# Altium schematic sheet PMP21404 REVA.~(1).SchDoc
size 431 x 279 mm; Date: Not shown in title block; ApprovedBy: Not shown in title block; CheckedBy: Not shown in title block; Author: Not shown in title block; CompanyName: Not shown in title block; Engineer: Not shown in title block; Organization: Not shown in title block; Address1: Not shown in title block; Address2: Not shown in title block; Address3: Not shown in title block; Address4: Not shown in title block; DocumentNumber: 1; Revision: Use project parameter SCH_Rev; SheetNumber: 1; SheetTotal: 1; PageSetup: Record=PageOptions¦CenterHorizontal=True¦CenterVertical=True¦PrintScale=1.00¦XCorrection=1.00¦YCorrection=1.00¦PrintKind=0¦BorderSize=5000000¦LeftOffset=0¦BottomOffset=0¦Orientation=2¦PaperLength=1000¦PaperWidth=1000¦Scale=100¦PaperSource=15¦PrintQuality=600¦MediaType=1¦DitherType=10¦PaperKind=Letter¦PrintScaleMode=1
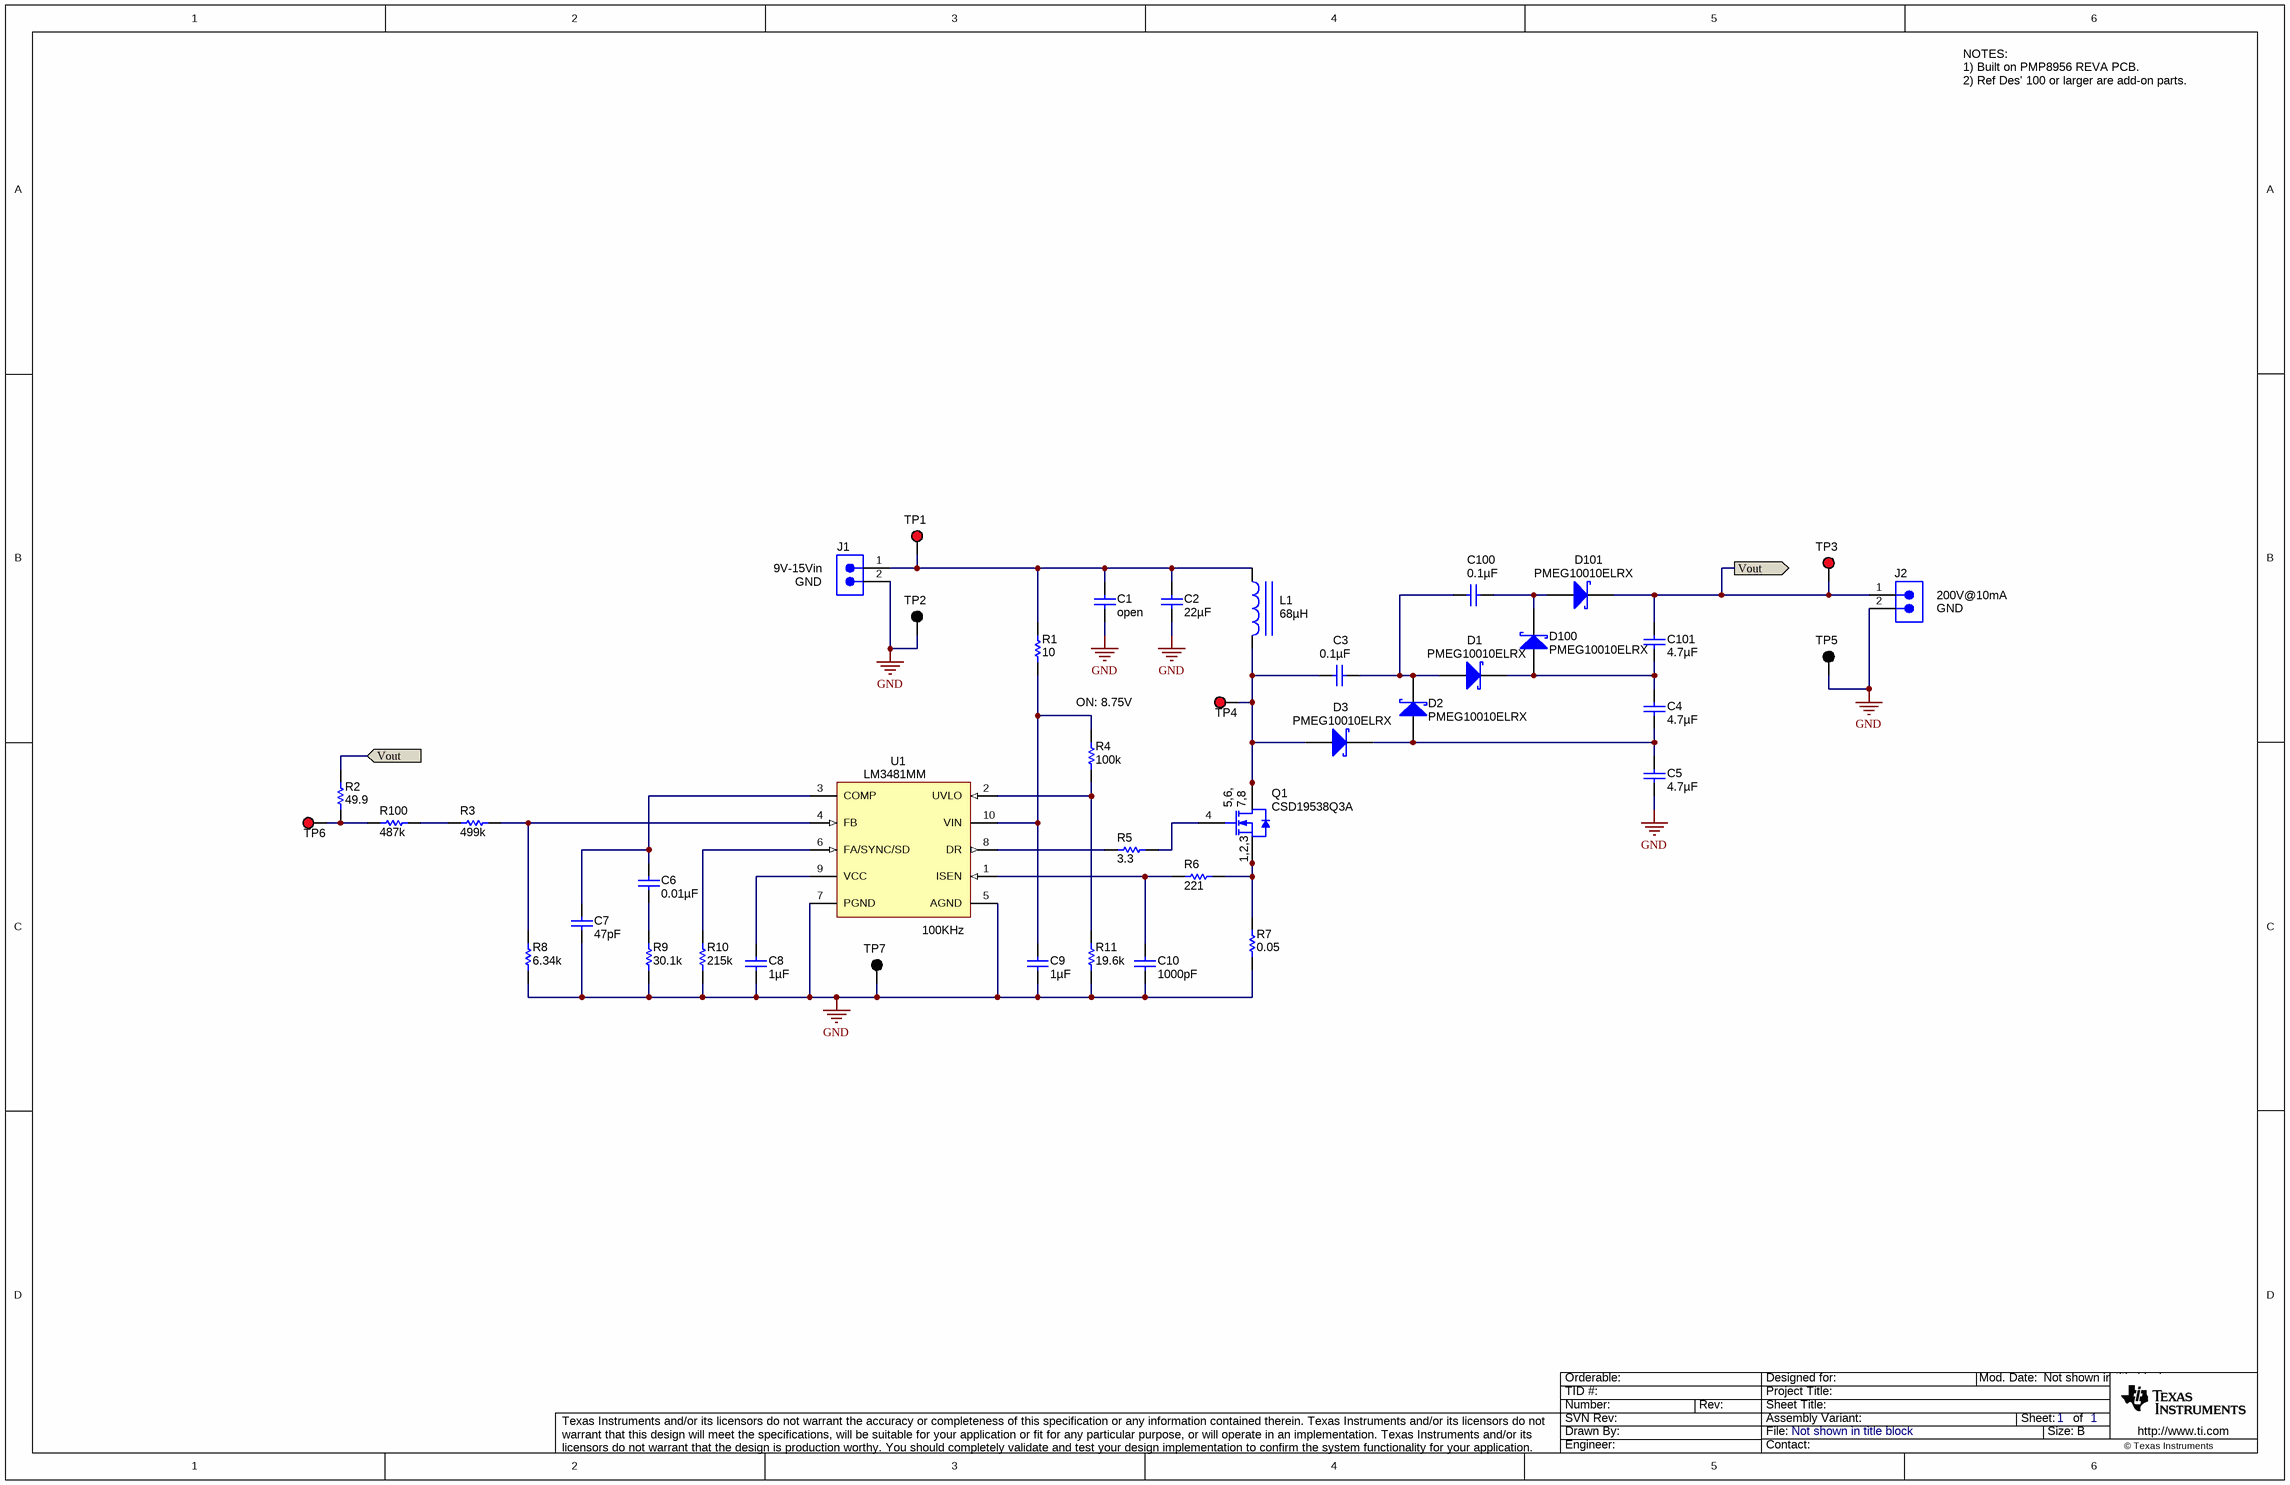
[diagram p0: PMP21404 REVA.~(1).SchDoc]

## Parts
C1  ValueDisplayed: open  [1206L]
C2  ValueDisplayed: 22µF  [1210]  (hidden comment: GRM32ER71E226ME15)
C3  ValueDisplayed: 0.1µF  [0805_HV]  (hidden comment: C2012X7R2A104K)
C4  ValueDisplayed: 4.7µF  [1210]  (hidden comment: C3225X7S2A475M)
C5  ValueDisplayed: 4.7µF  [1210]  (hidden comment: C3225X7S2A475M)
C6  ValueDisplayed: 0.01µF  [0603]  (hidden comment: C1608X7R1H103K)
C7  ValueDisplayed: 47pF  [0603]  (hidden comment: C1608C0G1H470J)
C8  ValueDisplayed: 1µF  [0603L]  (hidden comment: C1608X7R1C105K)
C9  ValueDisplayed: 1µF  [0805L]  (hidden comment: GRM21BR71H105KA12L)
C10  ValueDisplayed: 1000pF  [0603L]  (hidden comment: C1608X7R1H102K)
C100  ValueDisplayed: 0.1µF  [0805_HV]  (hidden comment: C2012X7R2A104K)
C101  ValueDisplayed: 4.7µF  [1210]  (hidden comment: C3225X7S2A475M)
D1  PMEG10010ELRX  [SOD-123W]
D2  PMEG10010ELRX  [SOD-123W]
D3  PMEG10010ELRX  [SOD-123W]
D100  PMEG10010ELRX  [SOD-123W]
D101  PMEG10010ELRX  [SOD-123W]
J1  ED555/2DS  [TERM_BLK_ED555-2DS]  (value not drawn)
J2  ED555/2DS  [TERM_BLK_ED555-2DS]  (value not drawn)
L1  ValueDisplayed: 68µH  [CLF7045]  (hidden comment: CLF7045NIT-680M-D)
Q1  CSD19538Q3A  [DNH0008A]
R1  value 10  [0603L]  (hidden comment: CRCW060310R0JNEA)
R2  value 49.9  [0603L]  (hidden comment: CRCW060349R9FKEA)
R3  ValueDisplayed: 499k  [0805_HV]  (hidden comment: CRCW0805499KFKEA)
R4  value 100k  [0603L]  (hidden comment: CRCW0603100KFKEA)
R5  ValueDisplayed: 3.3  [0603]  (hidden comment: CRCW06033R30JNEA)
R6  value 221  [0603L]  (hidden comment: CRCW0603221RFKEA)
R7  value 0.05  [0805L]  (hidden comment: CRM0805-FW-R050ELF)
R8  ValueDisplayed: 6.34k  [0603L]  (hidden comment: CRCW06036K34FKEA)
R9  ValueDisplayed: 30.1k  [0603]  (hidden comment: CRCW060330K1FKEA)
R10  value 215k  [0603]  (hidden comment: CRCW0603215KFKEA)
R11  value 19.6k  [0603L]  (hidden comment: CRCW060319K6FKEA)
R100  ValueDisplayed: 487k  [0805_HV]  (hidden comment: CRCW0805487KFKEA)
TP1  5000  [Keystone5000]  (value not drawn)
TP2  5001  [Keystone5001]  (value not drawn)
TP3  5000  [Keystone5000]  (value not drawn)
TP4  5000  [Keystone5000]  (value not drawn)
TP5  5001  [Keystone5001]  (value not drawn)
TP6  5000  [Keystone5000]  (value not drawn)
TP7  5001  [Keystone5001]  (value not drawn)
U1  LM3481MM  [MUB10A_L]

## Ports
Vout

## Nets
GND: C1.2 C2.2 C5.2 C7.2 C8.2 C9.2 C10.2 J1.2 J2.2 R7.1 R8.1 R9.1 R10.1 R11.1 TP2.1 TP5.1 TP7.1 U1.5(AGND) U1.7(PGND)
Vout: C101.1 D101.1(K) J2.1 R2.2 TP3.1 ; port Vout
NetC1_1: C1.1 C2.1 J1.1 L1.1 R1.2 TP1.1
NetC3_1: C3.1 C100.2 D1.2(A) D2.1(K)
NetC3_2: C3.2 D3.2(A) L1.2 Q1.5(D) Q1.6(D) Q1.7(D) Q1.8(D) Q1.9(D) TP4.1
NetC4_1: C4.1 C101.2 D1.1(K) D100.2(A)
NetC4_2: C4.2 C5.1 D2.2(A) D3.1(K)
NetC6_1: C6.1 C7.1 U1.3(COMP)
NetC6_2: C6.2 R9.2
NetC8_1: C8.1 U1.9(VCC)
NetC9_1: C9.1 R1.1 R4.2 U1.10(VIN)
NetC10_1: C10.1 R6.2 U1.1(ISEN)
NetC100_1: C100.1 D100.1(K) D101.2(A)
NetQ1_1: Q1.1(S) Q1.2(S) Q1.3(S) R6.1 R7.2
NetQ1_4: Q1.4(G) R5.2
NetR2_1: R2.1 R100.2 TP6.1
NetR3_1: R3.1 R8.2 U1.4(FB)
NetR3_2: R3.2 R100.1
NetR4_1: R4.1 R11.2 U1.2(UVLO)
NetR5_1: R5.1 U1.8(DR)
NetR10_2: R10.2 U1.6(FA/SYNC/SD)

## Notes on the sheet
- NOTES:
  1) Built on PMP8956 REVA PCB.
  2) Ref Des' 100 or larger are add-on parts.
- (near J1) 9V-15Vin
- (near J1) GND
- (near J2) 200V@10mA
- (near J2) GND
- ON: 8.75V
- (near U1) 100KHz

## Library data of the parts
C1 = C3216X7R2A104M: CAP, open, 1206; Polarized: N; CompType: Capacitor; U/M: EA; Cap_F: 0.0000001; Tolerance_%: 20; TaMin_C: -55; TaMax_C: 125
C2 = GRM32ER71E226KE15L: CAP, CERM, 22 µF, 25 V, +/- 10%, X7R, 1210; Manufacturer: MuRata; Polarized: N; CompType: Capacitor; Value: 22uF; U/M: EA; Cap_F: 0.000022; Tolerance_%: 10; Value1: Unknown; VDC_V: 25; Value2: 25V; TaMin_C: -55; TaMax_C: 125; AEC Category: Q200
C3 C100 = C2012X7R2A104K: CAP, CERM, 0.1uF, 100V, +/-10%, X7R, 0805; Manufacturer: TDK; Polarized: N; CompType: Capacitor; U/M: EA; Cap_F: 0.0000001; Tolerance_%: 10; ESR_Ohm: 0.0158; Value1: 0.0158 ohm; VDC_V: 100; TaMin_C: -55; TaMax_C: 125; Cap_Case: 0805
C4 C5 C101 = C3225X5R1E106K: CAP, CERM, 4.7uF, 100V, +/-20%, X7S, 1210; Manufacturer: TDK; Polarized: N; CompType: Capacitor; U/M: EA; Cap_F: 0.00001; Tolerance_%: 20; ESR_Ohm: 0.015; Value1: 0.015 ohm; VDC_V: 100; IRMS_A: 3; TaMin_C: -55; TaMax_C: 125
C6 = C1608X7R1H103K: CAP, CERM, 0.01uF, 50V, +/-10%, X7R, 0603; Manufacturer: TDK; Polarized: N; CompType: Capacitor; U/M: EA; Cap_F: 0.00000001; Tolerance_%: 10; ESR_Ohm: 0.0539; Value1: 0.0539 ohm; VDC_V: 50; TaMin_C: -55; TaMax_C: 125
C7 = C1608C0G1H470J: CAP, CERM, 47pF, 50V, +/-5%, C0G/NP0, 0603; Manufacturer: TDK; Polarized: N; CompType: Capacitor; U/M: EA; Cap_F: 0.000000000047; Tolerance_%: 5; ESR_Ohm: 0.22; Value1: 0.22 ohm; VDC_V: 50; TaMin_C: -55; TaMax_C: 125
C8 = C1608X7R1C105K: CAP, CERM, 1uF, 16V, +/-10%, X7R, 0603; Manufacturer: TDK; Polarized: N; CompType: Capacitor; U/M: EA; Cap_F: 0.000001; Tolerance_%: 10; ESR_Ohm: 0.0057; Value1: 0.0057 ohm; VDC_V: 16; TaMin_C: -55; TaMax_C: 125; Cap_Case: 0603
C9 = GRM21BR71H105KA12L: CAP, CERM, 1uF, 50V, +/-10%, X7R, 0805; Manufacturer: MuRata; Polarized: N; CompType: Capacitor; U/M: EA; Cap_F: 0.000001; Tolerance_%: 10; Value1: Unknown; VDC_V: 50; TaMin_C: -55; TaMax_C: 125; Cap_Case: 0805
C10 = C1608X7R1H102K: CAP, CERM, 1000pF, 50V, +/-10%, X7R, 0603; Manufacturer: TDK; Polarized: N; CompType: Capacitor; U/M: EA; Cap_F: 0.000000001; Tolerance_%: 10; ESR_Ohm: 0.24; Value1: 0.24 ohm; VDC_V: 50; TaMin_C: -55; TaMax_C: 125; Cap_Case: 0603
D1-D3 D100 D101 = PMEG10010ELRX: Diode, Schottky, 100 V, 1 A, AEC-Q101, SOD-123W; Manufacturer: NXP Semiconductor; U/M: EA; Vf_V: 0.77; Value: 100V; Value1: 1A; Value2: 0.77V; Io_A: 1; Vr_V: 100; TJmax_C: 175; AEC Category: Q101; AEC Qualified: Y
J1 J2 = ED555/2DS: Terminal Block, 6A, 3.5mm Pitch, 2-Pos, TH; Manufacturer: On-Shore Technology, Inc.; SymbolCreator: a0412235; CompType: Connector; U/M: EA
L1 = CLF7045T-680M: Inductor, Shielded, Ferrite, 68 µH, 1.1 A, 0.17 ohm, SMD; Manufacturer: TDK; Value: 68uH; Ind_H: 68.0E-6; Imax_A: 1.1; Irms: 0.95A @ 30C rise; Isat: 1.1A @ 10% inductance drop; DCR_ohm: 0.25; Value2: 1.1A; AEC Category: Q200
Q1 = CSD19538Q3A: MOSFET, N-CH, 100 V, 5 A, DNH0008A; Manufacturer: Texas Instruments; Alternate Manufacturer: None; U/M: EA; ChType: N; Value: 100V; VdsMax_V: 100; Value1: ? ohm; Value2: 7.2 nC; QgTyp_nC: 7.2; Vgs_V: 20; IdsMax_A: 5; AEC Category: Q101
R1 = CRCW060310R0JNEA: RES, 10 ohm, 1%, 0.1W, 0603; Manufacturer: Vishay-Dale; CompType: Resistor; Value_Code: 10R0; Tolerance_%: 5; Power_W: 0.1; VDC_V: 75; TempCo: 200 ppm/C; EIA_Code: E24; U/M: EA
R2 = CRCW060349R9FKEA: RES, 49.9 ohm, 1%, 0.1W, 0603; Manufacturer: Vishay-Dale; CompType: Resistor; Value_Code: 49R9; Tolerance_%: 1; Power_W: 0.1; VDC_V: 75; TempCo: 100 ppm/C; EIA_Code: E96; U/M: EA
R3 = CRCW0805499KFKEA: RES, 499 k, 1%, 0.125 W, 0805; Manufacturer: Vishay-Dale; CompType: Resistor; Value: 499k; Res_ohm: 499000; Tolerance_%: 1; Power_W: 0.125; Value2: 0.125W; VDC_V: 150; TempCo: 100 ppm/C; EIA_Code: E96; U/M: EA; AEC Category: Q200
R4 = CRCW0603100KFKEA: RES, 100k ohm, 1%, 0.1W, 0603; Manufacturer: Vishay-Dale; CompType: Resistor; Res_ohm: 100000; Tolerance_%: 1; Power_W: 0.1; VDC_V: 75; TempCo: 100 ppm/C; EIA_Code: E96; U/M: EA
R5 = CRCW06033R30JNEA: RES, 3.3, 5%, 0.1 W, 0603; Manufacturer: Vishay-Dale; CompType: Resistor; Value: 3.3; Value_Code: 3R30; Tolerance_%: 5; Power_W: 0.1; Value2: 0.1W; VDC_V: 75; TempCo: 200 ppm/C; EIA_Code: E24; U/M: EA; AEC Category: Q200
R6 = CRCW0603221RFKEA: RES, 221 ohm, 1%, 0.1W, 0603; Manufacturer: Vishay-Dale; CompType: Resistor; Value_Code: 221R; Tolerance_%: 1; Power_W: 0.1; VDC_V: 75; TempCo: 100 ppm/C; EIA_Code: E96; U/M: EA
R7 = CRM0805-FW-R050ELF: RES, 0.05 ohm, 1%, 0.1W, 0805; Manufacturer: Bourns; CompType: Resistor; Value_Code: R050; Tolerance_%: 1; Power_W: 0.25; Value2: 0.25W; VDC_V: 0; TempCo: 150 ppm/C; EIA_Code: E96; U/M: EA
R8 = CRCW06036K34FKEA: RES, 6.34 k, 1%, 0.1 W, 0603; Manufacturer: Vishay-Dale; CompType: Resistor; Value: 6.34k; Res_ohm: 6340; Value_Code: 6k34; Tolerance_%: 1; Power_W: 0.1; Value2: 0.1W; VDC_V: 75; TempCo: 100 ppm/C; EIA_Code: E96; U/M: EA; AEC Category: Q200
R9 = CRCW060330K1FKEA: RES, 30.1 k, 1%, 0.1 W, 0603; Manufacturer: Vishay-Dale; CompType: Resistor; Value: 30.1k; Res_ohm: 30100; Value_Code: 30k1; Tolerance_%: 1; Power_W: 0.1; Value2: 0.1W; VDC_V: 75; TempCo: 100 ppm/C; EIA_Code: E96; U/M: EA; AEC Category: Q200
R10 = CRCW0603215KFKEA: RES, 215k ohm, 1%, 0.1W, 0603; Manufacturer: Vishay-Dale; CompType: Resistor; Res_ohm: 215000; Tolerance_%: 1; Power_W: 0.1; VDC_V: 75; TempCo: 100 ppm/C; EIA_Code: E96; U/M: EA
R11 = CRCW060319K6FKEA: RES, 19.6k ohm, 1%, 0.1W, 0603; Manufacturer: Vishay-Dale; CompType: Resistor; Res_ohm: 19600; Value_Code: 19k6; Tolerance_%: 1; Power_W: 0.1; VDC_V: 75; TempCo: 100 ppm/C; EIA_Code: E96; U/M: EA
R100 = CRCW0805487KFKEA: RES, 487 k, 1%, 0.125 W, 0805; Manufacturer: Vishay-Dale; CompType: Resistor; Value: 487k; Res_ohm: 487000; Tolerance_%: 1; Power_W: 0.125; Value2: 0.125W; VDC_V: 150; TempCo: 100 ppm/C; EIA_Code: E96; U/M: EA; AEC Category: Q200
TP1 TP3 TP4 TP6 = 5000: Test Point, TH, Miniature, Red; Manufacturer: Keystone; CompType: Test Point Loop; U/M: EA
TP2 TP5 TP7 = 5001: Test Point, TH, Miniature, Black; Manufacturer: Keystone; CompType: Test Point Loop; U/M: EA
U1 = LM3481MM: High Efficiency Low-Side N-Channel Controller for Switching Regulators, 10-pin MSOP; Manufacturer: National Semiconductor; PackageTopMarking: ZXTT*SJPB; PowerWise: N; CompType: MiscPower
